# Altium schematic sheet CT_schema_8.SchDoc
size 277 x 170 mm
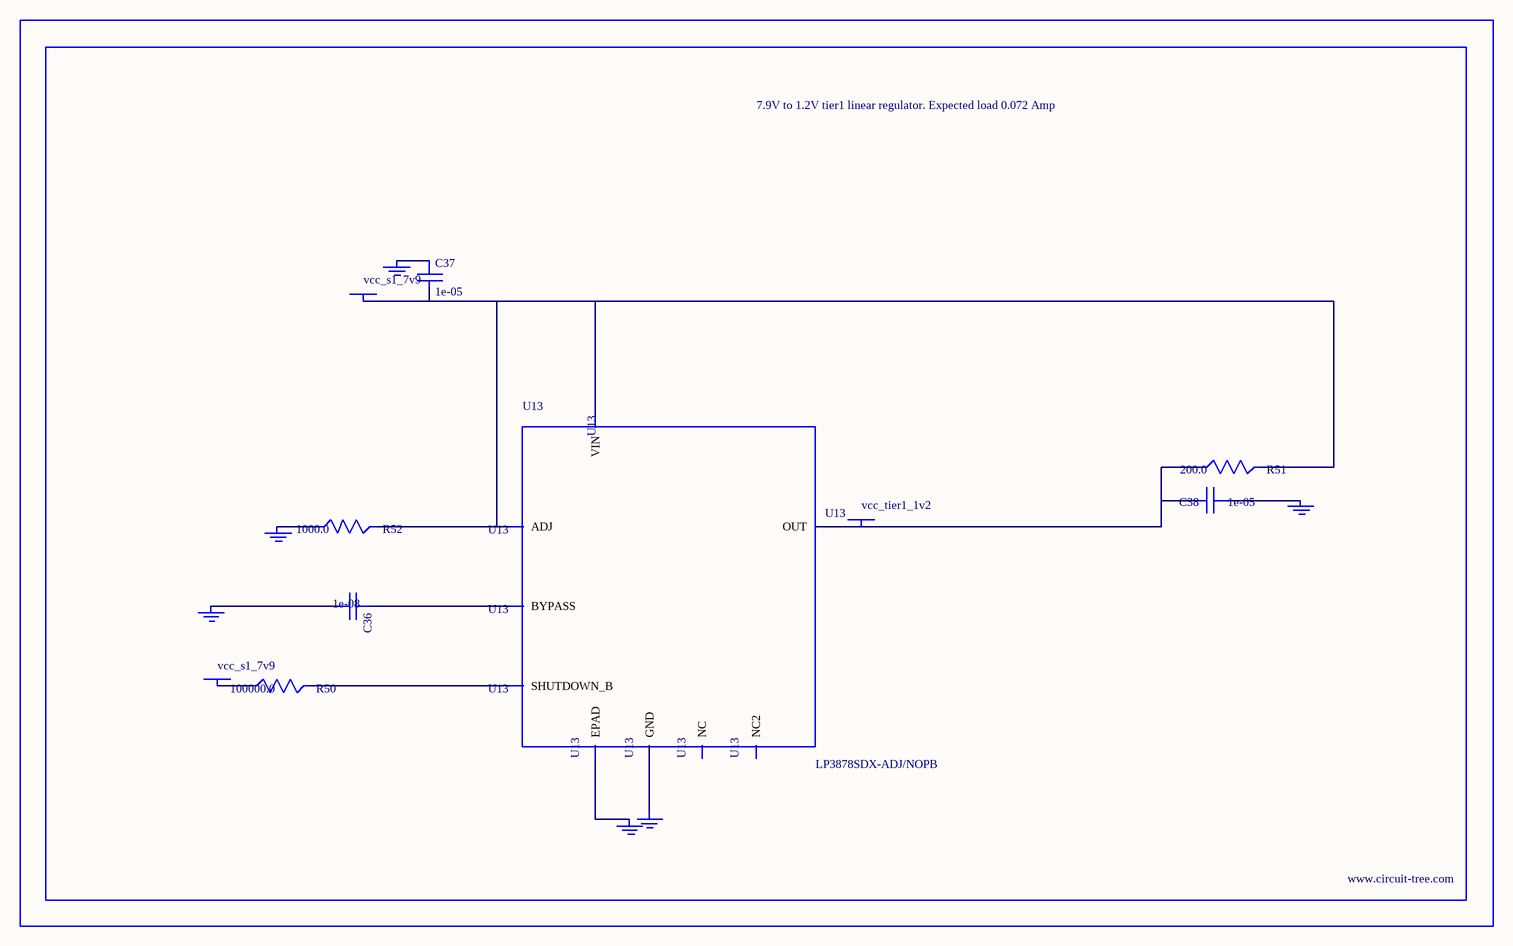
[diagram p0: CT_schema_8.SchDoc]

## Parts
BORDER7  (no value)
C36  1e-08  [C0402]
C37  1e-05  [C1206]
C38  1e-05  [C0805]
GND_INSTANCE_7_0  (no value)
GND_INSTANCE_7_1  (no value)
GND_INSTANCE_7_2  (no value)
GND_INSTANCE_7_3  (no value)
GND_INSTANCE_7_4  (no value)
GND_INSTANCE_7_5  (no value)
POWER_INSTANCE_7_0  vcc_s1_7v9
POWER_INSTANCE_7_1  vcc_s1_7v9
POWER_INSTANCE_7_2  vcc_tier1_1v2
R50  100000.0  [R0603]
R51  200.0  [R0603]
R52  1000.0  [R0603]
U13  LP3878SDX-ADJ/NOPB  [WSON-8]

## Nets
NetC36_1: C36.1 U13.1(BYPASS)
NetC36_2: C36.2 GND_INSTANCE_7_0.0(GND)
NetC37_1: C37.1 GND_INSTANCE_7_1.0(GND)
NetC37_2: C37.2 POWER_INSTANCE_7_0.0(PWR) R51.2 R52.2 U13.4(VIN) U13.6(ADJ)
NetC38_1: C38.1 GND_INSTANCE_7_2.0(GND)
NetC38_2: C38.2 POWER_INSTANCE_7_2.0(PWR) R51.1 U13.5(OUT)
NetGND_INSTANCE_7_3_0: GND_INSTANCE_7_3.0(GND) R52.1
NetGND_INSTANCE_7_4_0: GND_INSTANCE_7_4.0(GND) U13.PAD(EPAD)
NetGND_INSTANCE_7_5_0: GND_INSTANCE_7_5.0(GND) U13.3(GND)
NetPOWER_INSTANCE_7_1_0: POWER_INSTANCE_7_1.0(PWR) R50.1
NetR50_2: R50.2 U13.8(SHUTDOWN_B)

Not connected (* = marked no-connect by the designer): U13 2(NC) 7(NC2)

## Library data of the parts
BORDER7 = BORDER_PAGE7
C36 = C0402C103K3RAC
C37 = C1206C106K3RACTU
C38 = GRM219R60J106ME19D
GND_INSTANCE_7_0-GND_INSTANCE_7_5 = GND
POWER_INSTANCE_7_0-POWER_INSTANCE_7_2 = PWR
R50 = RC0603JR-07100KL
R51 = RC0603JR-07200RL
R52 = RC0603JR-071KL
